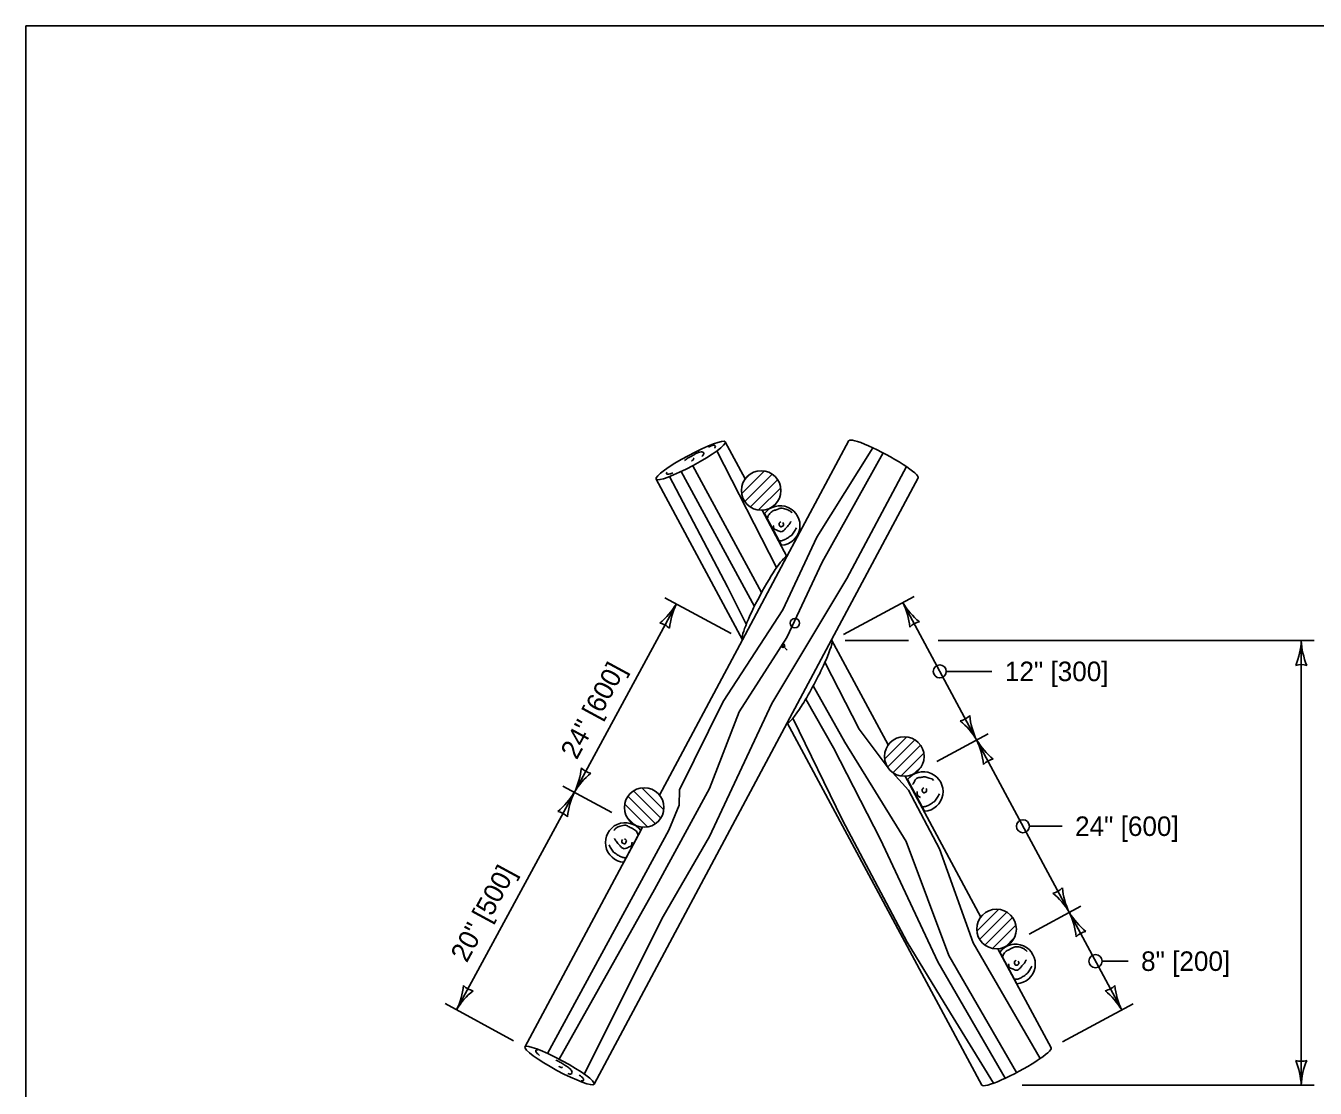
# Model space of a CAD drawing. Extents: x 49991.4 to 50021, y 49987.6 to 50011.4.
# Drawn here: x 49999.384 to 50003.345, y 49995.736 to 49998.999 of the extents above; entities that cross this region are included whole.
import ezdxf

# ---------------------------------------------------------------- set-up
doc = ezdxf.new("R2010")
doc.units = 0
for name, color, linetype in [('Level 1', 7, 'Continuous'), ('Level 2', 7, 'Continuous'), ('Level 3', 7, 'Continuous')]:
    doc.layers.add(name, color=color, linetype=linetype)

msp = doc.modelspace()

# ---------------------------------------------------------------- linework, layer by layer
at = {"layer": 'Level 1'}
for p, q in [((50001.5935, 49997.6075), (50001.5325, 49997.7211)), ((50001.7218, 49997.3687), (50001.9124, 49997.7251)), ((50001.5826, 49997.5619), (50001.6524, 49997.6317)), ((50001.592, 49997.6052), (50001.6091, 49997.6223)), ((50001.5923, 49997.5376), (50001.6767, 49997.622)), ((50001.5855, 49997.1131), (50001.3199, 49997.6066)), ((50001.6093, 49997.5207), (50001.6936, 49997.605)), ((50001.6339, 49997.5114), (50001.7029, 49997.5804)), ((50001.8591, 49997.1134), (50002.1247, 49997.6104)), ((50001.7218, 49997.3687), (50001.6454, 49997.5108)), ((50001.6526, 49997.501), (50001.705, 49997.4034)), ((50001.6801, 49997.5236), (50001.6907, 49997.5342)), ((50001.7218, 49997.3687), (50001.5855, 49997.1131)), ((50001.3305, 49996.6362), (50001.5855, 49997.1133)), ((50001.7226, 49996.8577), (50001.8591, 49997.1134)), ((50002.0328, 49996.79), (50001.8591, 49997.1134)), ((50001.7094, 49997.0955), (50001.7222, 49997.0812)), ((50001.1296, 49995.7481), (50001.7226, 49996.8577)), ((50002.3205, 49995.7453), (50001.7226, 49996.8577)), ((50002.0219, 49996.7468), (50002.09, 49996.8149)), ((50002.0309, 49996.7218), (50002.1149, 49996.8058)), ((50002.0476, 49996.7045), (50002.1322, 49996.7892)), ((50002.0716, 49996.6946), (50002.1422, 49996.7652)), ((50002.1128, 49996.7019), (50002.1349, 49996.7239)), ((50002.3171, 49996.2612), (50002.0846, 49996.6937)), ((50002.0922, 49996.6839), (50002.1445, 49996.5863)), ((50001.318, 49996.548), (50001.2333, 49996.6327)), ((50001.3346, 49996.5653), (50001.2507, 49996.6493)), ((50001.3436, 49996.5903), (50001.2756, 49996.6583)), ((50001.294, 49996.538), (50001.2234, 49996.6087)), ((50001.253, 49996.5451), (50001.2305, 49996.5677)), ((50000.9167, 49995.862), (50001.2777, 49996.5373)), ((50001.2734, 49996.5273), (50001.221, 49996.4297)), ((50002.3052, 49996.2183), (50002.3721, 49996.2851)), ((50002.3138, 49996.1929), (50002.3974, 49996.2765)), ((50002.3301, 49996.1753), (50002.4151, 49996.2602)), ((50002.3537, 49996.165), (50002.4254, 49996.2366)), ((50002.3929, 49996.1702), (50002.4202, 49996.1975)), ((50002.533, 49995.8595), (50002.3695, 49996.1639)), ((50002.3756, 49996.154), (50002.428, 49996.0564))]:
    msp.add_line(p, q, dxfattribs=at)
msp.add_lwpolyline([(49999.3835, 49998.9992), (50016.7501, 49998.9992), (50016.7501, 49987.7988), (49999.3835, 49987.7988)], close=True, dxfattribs=at)
for points in [[(50000.986, 49995.8427), (50001.3588, 49996.5281), (50001.3905, 49996.6056), (50001.3916, 49996.6526), (50001.5259, 49996.9232), (50001.7091, 49997.2047), (50001.8139, 49997.4286), (50001.9852, 49997.7032)], [(50001.0224, 49995.8248), (50001.3146, 49996.3458), (50001.4842, 49996.6559), (50001.5752, 49996.8918), (50001.7212, 49997.12), (50001.8297, 49997.3516), (50002.0176, 49997.6872)], [(50001.5063, 49997.6932), (50001.6898, 49997.3347)], [(50001.0989, 49995.779), (50001.3418, 49996.2633), (50001.4842, 49996.5084), (50001.6755, 49996.9177), (50001.9056, 49997.3013), (50002.0886, 49997.6453)], [(50001.3969, 49997.6301), (50001.6218, 49997.2158)], [(50001.4323, 49997.6479), (50001.6439, 49997.2584)], [(50001.3609, 49997.6144), (50001.5394, 49997.2763), (50001.597, 49997.1612)], [(50001.8384, 49997.0441), (50001.9438, 49996.8383), (50002.0298, 49996.7236), (50002.03, 49996.7234)], [(50001.8025, 49996.9715), (50001.8994, 49996.799), (50002.0877, 49996.4931), (50002.2195, 49996.143), (50002.4273, 49995.7836)], [(50001.7797, 49996.9312), (50001.8644, 49996.7808), (50002.0089, 49996.4996), (50002.1849, 49996.1241), (50002.3923, 49995.7662)], [(50001.7402, 49996.8719), (50001.8923, 49996.5586), (50002.0909, 49996.1846), (50002.2048, 49995.9976), (50002.3565, 49995.7513)], [(50002.0458, 49996.7058), (50002.095, 49996.6511), (50002.1908, 49996.4711), (50002.2937, 49996.1821), (50002.4994, 49995.8265)]]:
    msp.add_lwpolyline(points, dxfattribs=at)
for centre, radius in [((50001.6427, 49997.5716), 0.0608), ((50001.7464, 49997.1644), 0.0144), ((50001.7101, 49997.0948), 0.00499), ((50002.0823, 49996.7545), 0.0608), ((50001.2832, 49996.5979), 0.0608), ((50002.3657, 49996.2246), 0.0608)]:
    msp.add_circle(centre, radius, dxfattribs=at)
for centre, start, end in [((50001.701, 49997.4641), 273.7846, 142.611), ((50002.1405, 49996.647), 273.7846, 142.611), ((50001.225, 49996.4904), 37.389, 266.2154), ((50002.424, 49996.1171), 273.7846, 142.611)]:
    msp.add_arc(centre, 0.0608, start, end, dxfattribs=at)
for centre, major_axis in [((50001.4262, 49997.6638), (0.1063, 0.0572)), ((50001.0232, 49995.8053), (0.1063, -0.0572))]:
    msp.add_ellipse(centre, major_axis=major_axis, ratio=0.139914, dxfattribs=at)
for centre, major_axis, ratio, start_param, end_param in [((50002.0185, 49997.6676), (0.1063, -0.0572), 0.139914, 6.283128, 9.42717), ((50001.6537, 49997.2409), (0.0682, 0.1278), 0.116361, 6.280826, 9.42101), ((50001.7909, 49996.9855), (0.0682, 0.1278), 0.116361, 3.125187, 6.282291), ((50002.4267, 49995.8024), (0.1063, 0.0572), 0.139914, 3.141793, 6.283506)]:
    msp.add_ellipse(centre, major_axis=major_axis, ratio=ratio, start_param=start_param, end_param=end_param, dxfattribs=at)
for points in [[(50001.4812, 49997.7052), (50001.4889, 49997.7087), (50001.4974, 49997.7109), (50001.5016, 49997.7091), (50001.5022, 49997.7075), (50001.5005, 49997.7031), (50001.4999, 49997.7017)], [(50001.4069, 49997.6638), (50001.4149, 49997.6698), (50001.4275, 49997.6766), (50001.4393, 49997.6835), (50001.4512, 49997.689), (50001.4579, 49997.6905), (50001.4634, 49997.6896), (50001.466, 49997.687), (50001.4665, 49997.6835), (50001.4648, 49997.6809), (50001.4603, 49997.6762)], [(50001.4338, 49997.6698), (50001.4357, 49997.6703), (50001.4361, 49997.6691), (50001.4336, 49997.6663), (50001.4323, 49997.6652), (50001.4296, 49997.6629), (50001.4283, 49997.6632)], [(50001.3538, 49997.6282), (50001.3516, 49997.6259), (50001.3516, 49997.6233), (50001.3545, 49997.6216), (50001.3618, 49997.6224), (50001.3711, 49997.6256)], [(50001.738, 49997.5028), (50001.728, 49997.5105), (50001.7146, 49997.5156), (50001.6997, 49997.5169), (50001.6891, 49997.5124), (50001.6787, 49997.5092), (50001.6691, 49997.5008), (50001.6648, 49997.4958), (50001.6627, 49997.4877)], [(50001.734, 49997.4767), (50001.733, 49997.4747), (50001.7282, 49997.4672), (50001.7182, 49997.4556), (50001.7124, 49997.4491), (50001.7045, 49997.4451), (50001.6976, 49997.4466), (50001.6912, 49997.4496), (50001.6818, 49997.4546), (50001.6802, 49997.4627), (50001.6796, 49997.4647)], [(50001.7096, 49997.4734), (50001.7112, 49997.4648), (50001.7059, 49997.4608), (50001.7017, 49997.4603), (50001.699, 49997.4638), (50001.6974, 49997.4694), (50001.7027, 49997.4759)], [(50001.7508, 49997.4573), (50001.7429, 49997.4433), (50001.7386, 49997.4372), (50001.7291, 49997.4292), (50001.718, 49997.4222), (50001.708, 49997.4181), (50001.6974, 49997.4171), (50001.6968, 49997.4171)], [(50002.1724, 49996.6814), (50002.1666, 49996.6859), (50002.1586, 49996.6879), (50002.1465, 49996.6919), (50002.1359, 49996.6909), (50002.1243, 49996.6889), (50002.1159, 49996.6829), (50002.1138, 49996.6779), (50002.1074, 49996.6683)], [(50002.1322, 49996.6282), (50002.1254, 49996.6332), (50002.1222, 49996.6412), (50002.1222, 49996.6472)], [(50002.1903, 49996.6402), (50002.1824, 49996.6262), (50002.1782, 49996.6201), (50002.1687, 49996.6121), (50002.1576, 49996.6051), (50002.1475, 49996.601), (50002.137, 49996.6001), (50002.1364, 49996.6001)], [(50002.1491, 49996.6563), (50002.1507, 49996.6477), (50002.1454, 49996.6438), (50002.1412, 49996.6432), (50002.1386, 49996.6468), (50002.137, 49996.6523), (50002.1423, 49996.6588)], [(50001.1902, 49996.5269), (50001.1968, 49996.5347), (50001.2099, 49996.5409), (50001.2263, 49996.5432), (50001.2368, 49996.5387), (50001.2437, 49996.5352), (50001.2569, 49996.5271), (50001.2611, 49996.5221), (50001.2633, 49996.5141)], [(50001.1752, 49996.4836), (50001.1831, 49996.4696), (50001.1873, 49996.4635), (50001.1968, 49996.4555), (50001.2079, 49996.4485), (50001.218, 49996.4444), (50001.2285, 49996.4435), (50001.2292, 49996.4435)], [(50001.1919, 49996.503), (50001.193, 49996.501), (50001.1977, 49996.4935), (50001.2078, 49996.4819), (50001.2136, 49996.4754), (50001.2215, 49996.4714), (50001.2284, 49996.4729), (50001.2347, 49996.4759), (50001.2442, 49996.4809), (50001.2458, 49996.489), (50001.2463, 49996.491)], [(50001.2164, 49996.4997), (50001.2148, 49996.4911), (50001.2201, 49996.4872), (50001.2243, 49996.4866), (50001.2269, 49996.4902), (50001.2285, 49996.4957), (50001.2232, 49996.5022)], [(50002.4597, 49996.1556), (50002.4519, 49996.1625), (50002.4378, 49996.1687), (50002.4227, 49996.1699), (50002.4122, 49996.1654), (50002.4053, 49996.1618), (50002.3921, 49996.1538), (50002.3879, 49996.1488), (50002.3857, 49996.1408)], [(50002.457, 49996.1297), (50002.456, 49996.1277), (50002.4512, 49996.1202), (50002.4412, 49996.1086), (50002.4354, 49996.1021), (50002.4275, 49996.0981), (50002.4206, 49996.0996), (50002.4143, 49996.1026), (50002.4048, 49996.1076), (50002.4032, 49996.1157), (50002.4026, 49996.1177)], [(50002.4326, 49996.1264), (50002.4342, 49996.1178), (50002.4289, 49996.1138), (50002.4247, 49996.1133), (50002.422, 49996.1169), (50002.4205, 49996.1224), (50002.4257, 49996.1289)], [(50002.4738, 49996.1103), (50002.4659, 49996.0963), (50002.4617, 49996.0902), (50002.4521, 49996.0822), (50002.441, 49996.0752), (50002.431, 49996.0711), (50002.4205, 49996.0702), (50002.4198, 49996.0702)], [(50000.9562, 49995.8525), (50000.953, 49995.8535), (50000.9508, 49995.8521), (50000.9505, 49995.8488), (50000.9548, 49995.8426), (50000.9619, 49995.836)], [(50001.0123, 49995.8223), (50001.0215, 49995.818), (50001.0334, 49995.8102), (50001.045, 49995.8029), (50001.0555, 49995.795), (50001.0599, 49995.7899), (50001.0617, 49995.7845), (50001.0605, 49995.7811), (50001.0578, 49995.7789), (50001.0547, 49995.7791), (50001.0484, 49995.781)], [(50001.0303, 49995.8013), (50001.0317, 49995.7999), (50001.0308, 49995.799), (50001.0272, 49995.7998), (50001.0256, 49995.8006), (50001.0223, 49995.8019), (50001.022, 49995.8031)], [(50001.084, 49995.7762), (50001.0906, 49995.771), (50001.0964, 49995.7645), (50001.097, 49995.76), (50001.0957, 49995.7587), (50001.091, 49995.7582), (50001.0895, 49995.758)]]:
    msp.add_spline(points, degree=3, dxfattribs=at)
at = {"layer": 'Level 3'}
for p, q in [((50001.0687, 49996.6446), (50001.3821, 49997.2232)), ((50001.5502, 49997.1321), (50001.3469, 49997.2422)), ((50001.8958, 49997.1296), (50002.113, 49997.2463)), ((50002.3045, 49996.8054), (50002.0778, 49997.2273)), ((50001.9006, 49997.1106), (50002.0951, 49997.1106)), ((50002.1859, 49997.1106), (50003.3418, 49997.1106)), ((50003.3018, 49995.7449), (50003.3018, 49997.1106)), ((50002.2113, 49997.0161), (50002.3513, 49997.0161)), ((50002.1819, 49996.739), (50002.3397, 49996.8244)), ((50002.589, 49996.276), (50002.3045, 49996.8054)), ((50000.7067, 49995.9764), (50001.0687, 49996.6446)), ((50001.1836, 49996.5823), (50001.0335, 49996.6637)), ((50002.4669, 49996.5405), (50002.5669, 49996.5405)), ((50002.4654, 49996.209), (50002.6242, 49996.2951)), ((50002.7502, 49995.9763), (50002.589, 49996.276)), ((50002.6897, 49996.1259), (50002.7697, 49996.1259)), ((50000.6715, 49995.9954), (50000.8817, 49995.8815)), ((50002.7854, 49995.9952), (50002.5682, 49995.8785)), ((50002.4441, 49995.7449), (50003.3418, 49995.7449))]:
    msp.add_line(p, q, dxfattribs=at)
for centre in [(50002.1913, 49997.0161), (50002.4469, 49996.5405), (50002.6697, 49996.1259)]:
    msp.add_circle(centre, 0.02, dxfattribs=at)
for centre, radius, start, end in [((50001.1911, 49997.3371), 0.2223, 309.0108, 329.1943), ((50001.5922, 49997.1225), 0.233, 154.3821, 173.6319), ((50001.8778, 49997.1302), 0.2223, 5.7119, 25.8955), ((50002.2773, 49997.3476), 0.233, 211.0832, 230.3331), ((50001.321, 49997.1105), 0.0548, 43.6936, 79.4159), ((50002.1385, 49997.1144), 0.0548, 100.3948, 136.1171), ((50003.0796, 49997.1198), 0.2223, 337.456, 357.6395), ((50003.5345, 49997.1221), 0.233, 182.8273, 202.0772), ((50003.3018, 49996.9824), 0.0548, 72.1388, 107.8612), ((50002.2438, 49996.9183), 0.0548, 280.3948, 316.1171), ((50002.105, 49996.6851), 0.233, 31.0832, 50.3331), ((50002.5045, 49996.9025), 0.2223, 185.7119, 205.8955), ((50002.1045, 49996.7083), 0.2223, 5.7119, 25.8955), ((50002.5041, 49996.9257), 0.233, 211.0832, 230.3331), ((50002.3652, 49996.6925), 0.0548, 100.3948, 136.1171), ((50000.8586, 49996.7454), 0.233, 334.3821, 353.6319), ((50001.1297, 49996.7573), 0.0548, 223.6936, 259.4159), ((50001.2596, 49996.5308), 0.2223, 129.0108, 149.1943), ((50000.8777, 49996.7585), 0.2223, 309.0108, 329.1943), ((50001.2788, 49996.5439), 0.233, 154.3821, 173.6319), ((50001.0076, 49996.5319), 0.0548, 43.6936, 79.4159), ((50002.5283, 49996.389), 0.0548, 280.3948, 316.1171), ((50002.789, 49996.3731), 0.2223, 185.7119, 205.8955), ((50002.3895, 49996.1558), 0.233, 31.0832, 50.3331), ((50002.389, 49996.1789), 0.2223, 5.7119, 25.8955), ((50002.7886, 49996.3963), 0.233, 211.0832, 230.3331), ((50002.6497, 49996.1631), 0.0548, 100.3948, 136.1171), ((50000.4966, 49996.0771), 0.233, 334.3821, 353.6319), ((50000.8976, 49995.8625), 0.2223, 129.0108, 149.1943), ((50000.7677, 49996.0891), 0.0548, 223.6936, 259.4159), ((50002.6895, 49996.0892), 0.0548, 280.3948, 316.1171), ((50002.5506, 49995.856), 0.233, 31.0832, 50.3331), ((50002.9502, 49996.0733), 0.2223, 185.7119, 205.8955), ((50003.3018, 49995.8731), 0.0548, 252.1388, 287.8612), ((50003.069, 49995.7334), 0.233, 2.8273, 22.0772), ((50003.5239, 49995.7358), 0.2223, 157.456, 177.6395)]:
    msp.add_arc(centre, radius, start, end, dxfattribs=at)

# ---------------------------------------------------------------- texts
at = {"layer": 'Level 2'}
for s, p in [('24" [600]', (50001.076, 49996.7421)), ('20" [500]', (50000.7383, 49996.1187))]:
    msp.add_text(s, height=0.06, rotation=61.5548, dxfattribs=at).set_placement(p)
for s, p in [('12" [300]', (50002.3913, 49996.9861)), ('24" [600]', (50002.6069, 49996.5105)), ('8" [200]', (50002.8097, 49996.0959))]:
    msp.add_text(s, height=0.06, dxfattribs=at).set_placement(p)

doc.saveas('drawing.dxf')
